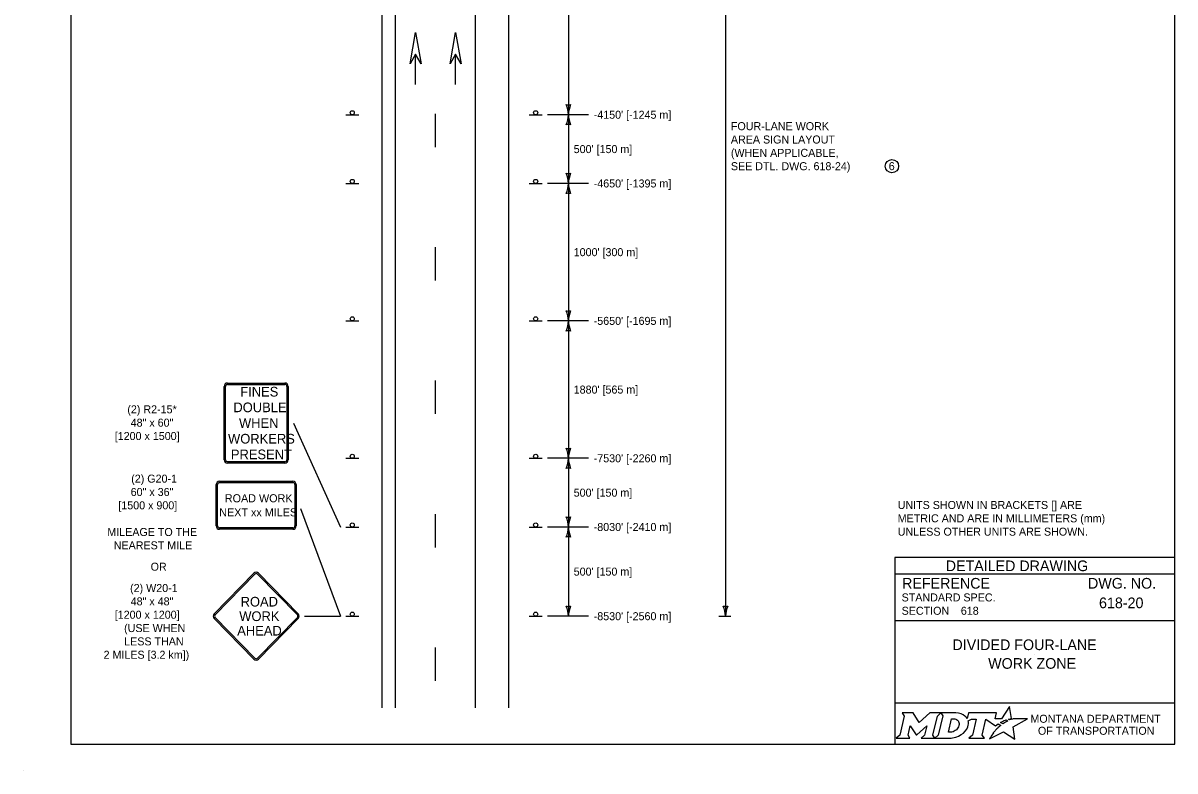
# Model space of a CAD drawing. Extents: x 49991.4 to 50021, y 49987.6 to 50011.4.
# Drawn here: x 49999.98 to 50008.61, y 49999.86 to 50005.47 of the extents above; entities that cross this region are included whole.
import ezdxf

# ---------------------------------------------------------------- set-up
doc = ezdxf.new("R2010")
doc.units = 0
for name, color, linetype in [('Level 1', 7, 'Continuous'), ('Level 2', 7, 'Continuous'), ('Level 3', 7, 'Continuous')]:
    doc.layers.add(name, color=color, linetype=linetype)

msp = doc.modelspace()

# ---------------------------------------------------------------- linework, layer by layer
at = {"layer": 'Level 1'}
for p, q in [((50002.6707, 50000.3351), (50002.6707, 50009.0553)), ((50002.7707, 50000.3351), (50002.7707, 50009.0553)), ((50003.3707, 50000.3351), (50003.3707, 50009.0553)), ((50003.6207, 50000.3351), (50003.6207, 50009.0553)), ((50002.9204, 50005.0081), (50002.9204, 50005.234)), ((50002.9207, 50005.0081), (50002.9207, 50005.234)), ((50003.2204, 50005.0081), (50003.2204, 50005.234)), ((50003.2207, 50005.0081), (50003.2207, 50005.234)), ((50002.3977, 50004.7808), (50002.4937, 50004.7808)), ((50003.0707, 50004.5379), (50003.0707, 50004.7879)), ((50003.7727, 50004.7808), (50003.8687, 50004.7808)), ((50002.3977, 50004.2658), (50002.4937, 50004.2658)), ((50003.7727, 50004.2658), (50003.8687, 50004.2658)), ((50003.0707, 50003.5379), (50003.0707, 50003.7879)), ((50002.3977, 50003.2358), (50002.4937, 50003.2358)), ((50003.7727, 50003.2358), (50003.8687, 50003.2358)), ((50001.4852, 50002.1951), (50001.4852, 50002.7451)), ((50001.4952, 50002.1951), (50001.4952, 50002.7451)), ((50001.5102, 50002.7701), (50001.9402, 50002.7701)), ((50001.5102, 50002.7601), (50001.9402, 50002.7601)), ((50001.9552, 50002.7451), (50001.9552, 50002.1951)), ((50001.9652, 50002.7451), (50001.9652, 50002.1951)), ((50003.0707, 50002.5379), (50003.0707, 50002.7879)), ((50002.3977, 50002.2058), (50002.4937, 50002.2058)), ((50003.7727, 50002.2058), (50003.8687, 50002.2058)), ((50001.9402, 50002.1801), (50001.5102, 50002.1801)), ((50001.9402, 50002.1701), (50001.5102, 50002.1701)), ((50001.4502, 50002.0334), (50002.0002, 50002.0334)), ((50001.4502, 50002.0334), (50002.0002, 50002.0334)), ((50001.4502, 50002.0234), (50002.0002, 50002.0234)), ((50001.4502, 50002.0234), (50002.0002, 50002.0234)), ((50001.4252, 50001.6984), (50001.4252, 50002.0084)), ((50001.4252, 50001.6984), (50001.4252, 50002.0084)), ((50001.4352, 50001.6984), (50001.4352, 50002.0084)), ((50001.4352, 50001.6984), (50001.4352, 50002.0084)), ((50002.0152, 50002.0084), (50002.0152, 50001.6984)), ((50002.0152, 50002.0084), (50002.0152, 50001.6984)), ((50002.0252, 50002.0084), (50002.0252, 50001.6984)), ((50002.0252, 50002.0084), (50002.0252, 50001.6984)), ((50003.0707, 50001.5379), (50003.0707, 50001.7879)), ((50002.0002, 50001.6834), (50001.4502, 50001.6834)), ((50002.0002, 50001.6834), (50001.4502, 50001.6834)), ((50002.0002, 50001.6734), (50001.4502, 50001.6734)), ((50002.0002, 50001.6734), (50001.4502, 50001.6734)), ((50002.3977, 50001.6908), (50002.4937, 50001.6908)), ((50003.7727, 50001.6908), (50003.8687, 50001.6908)), ((50001.7079, 50001.3439), (50001.4099, 50001.0399)), ((50001.7079, 50001.3439), (50001.4099, 50001.0399)), ((50001.7148, 50001.3369), (50001.4168, 50001.0328)), ((50001.7148, 50001.3369), (50001.4168, 50001.0328)), ((50002.0336, 50001.0328), (50001.7356, 50001.3369)), ((50002.0336, 50001.0328), (50001.7356, 50001.3369)), ((50002.0405, 50001.0399), (50001.7425, 50001.3439)), ((50002.0405, 50001.0399), (50001.7425, 50001.3439)), ((50001.4099, 50001.0045), (50001.7079, 50000.7005)), ((50001.4099, 50001.0045), (50001.7079, 50000.7005)), ((50001.4168, 50001.0116), (50001.7148, 50000.7075)), ((50001.4168, 50001.0116), (50001.7148, 50000.7075)), ((50001.7356, 50000.7075), (50002.0336, 50001.0116)), ((50001.7356, 50000.7075), (50002.0336, 50001.0116)), ((50001.7425, 50000.7005), (50002.0405, 50001.0045)), ((50001.7425, 50000.7005), (50002.0405, 50001.0045)), ((50002.3977, 50001.0222), (50002.4937, 50001.0222)), ((50003.7727, 50001.0222), (50003.8687, 50001.0222)), ((50003.0707, 50000.5379), (50003.0707, 50000.7879)), ((49999.9766, 49999.8624), (49999.9766, 49999.8624))]:
    msp.add_line(p, q, dxfattribs=at)
for points in [[(50008.6146, 50011.2628), (50000.3356, 50011.2628), (50000.3356, 50000.0624), (50008.6146, 50000.0624)], [(50002.8787, 50005.1617), (50002.9204, 50005.3982), (50002.9623, 50005.1617), (50002.9204, 50005.2339)], [(50003.1787, 50005.1617), (50003.2204, 50005.3982), (50003.2623, 50005.1617), (50003.2204, 50005.2339)]]:
    msp.add_lwpolyline(points, close=True, dxfattribs=at)
for centre in [(50002.4457, 50004.796), (50003.8207, 50004.796), (50002.4457, 50004.281), (50003.8207, 50004.281), (50002.4457, 50003.251), (50003.8207, 50003.251), (50002.4457, 50002.221), (50003.8207, 50002.221), (50002.4457, 50001.706), (50003.8207, 50001.706), (50002.4457, 50001.0374), (50003.8207, 50001.0374)]:
    msp.add_circle(centre, 0.0152, dxfattribs=at)
for centre, radius, start, end in [((50001.5102, 50002.7451), 0.025, 90, 180), ((50001.5102, 50002.7451), 0.015, 90, 180), ((50001.9402, 50002.7451), 0.025, 0, 90), ((50001.9402, 50002.7451), 0.015, 0, 90), ((50001.5102, 50002.1951), 0.025, 180, 270), ((50001.5102, 50002.1951), 0.015, 180, 270), ((50001.9402, 50002.1951), 0.025, 270, 0), ((50001.9402, 50002.1951), 0.015, 270, 0), ((50001.4502, 50002.0084), 0.025, 90, 180), ((50001.4502, 50002.0084), 0.025, 90, 180), ((50001.4502, 50002.0084), 0.015, 90, 180), ((50001.4502, 50002.0084), 0.015, 90, 180), ((50002.0002, 50002.0084), 0.025, 0, 90), ((50002.0002, 50002.0084), 0.025, 0, 90), ((50002.0002, 50002.0084), 0.015, 0, 90), ((50002.0002, 50002.0084), 0.015, 0, 90), ((50001.4502, 50001.6984), 0.025, 180, 270), ((50001.4502, 50001.6984), 0.025, 180, 270), ((50001.4502, 50001.6984), 0.015, 180, 270), ((50001.4502, 50001.6984), 0.015, 180, 270), ((50002.0002, 50001.6984), 0.025, 270, 360), ((50002.0002, 50001.6984), 0.015, 270, 360), ((50002.0002, 50001.6984), 0.025, 270, 360), ((50002.0002, 50001.6984), 0.015, 270, 360)]:
    msp.add_arc(centre, radius, start, end, dxfattribs=at)
for centre, major_axis, start_param, end_param in [((50001.7252, 50001.3262), (0, 0.025), 5.497787, 7.068583), ((50001.7252, 50001.3262), (0, 0.025), 5.497787, 7.068583), ((50001.7252, 50001.3262), (0, 0.015), 5.497787, 7.068583), ((50001.7252, 50001.3262), (0, 0.015), 5.497787, 7.068583), ((50001.4272, 50001.0222), (0, 0.025), 0.785398, 2.356194), ((50001.4272, 50001.0222), (0, 0.025), 0.785398, 2.356194), ((50001.4272, 50001.0222), (0, 0.015), 0.785398, 2.356194), ((50001.4272, 50001.0222), (0, 0.015), 0.785398, 2.356194), ((50002.0232, 50001.0222), (0, 0.015), 3.926991, 5.497791), ((50002.0232, 50001.0222), (0, 0.015), 3.926991, 5.497791), ((50002.0232, 50001.0222), (0, 0.025), 3.926991, 5.497791), ((50002.0232, 50001.0222), (0, 0.025), 3.926991, 5.497791), ((50001.7252, 50000.7181), (0, -0.025), 5.497787, 7.068576), ((50001.7252, 50000.7181), (0, -0.025), 5.497787, 7.068576), ((50001.7252, 50000.7181), (0, -0.015), 5.497787, 7.068576), ((50001.7252, 50000.7181), (0, -0.015), 5.497787, 7.068576)]:
    msp.add_ellipse(centre, major_axis=major_axis, ratio=0.98, start_param=start_param, end_param=end_param, dxfattribs=at)
at = {"layer": 'Level 2'}
for p, q in [((50008.6146, 50001.4624), (50006.5146, 50001.4624)), ((50006.5146, 50001.4624), (50006.5146, 50000.0624)), ((50008.6146, 50001.3374), (50006.5146, 50001.3374)), ((50008.2507, 50001.1223), (50008.2507, 50001.1223)), ((50008.6146, 50000.9874), (50006.5146, 50000.9874)), ((50007.0089, 50001.0629), (50007.0089, 50001.0629)), ((50007.5646, 50000.7383), (50007.5646, 50000.7383)), ((50008.6146, 50000.3693), (50006.5146, 50000.3693))]:
    msp.add_line(p, q, dxfattribs=at)
for points in [[(50006.5701, 50000.2974), (50006.5842, 50000.274), (50006.5507, 50000.1307), (50006.525, 50000.1082), (50006.6266, 50000.1082), (50006.6131, 50000.131), (50006.6293, 50000.2011), (50006.673, 50000.1321), (50006.6783, 50000.1321), (50006.7534, 50000.2016), (50006.737, 50000.1305), (50006.7123, 50000.1085), (50006.8139, 50000.1085), (50006.8001, 50000.1318), (50006.8333, 50000.2742)], [(50006.8333, 50000.2742), (50006.8586, 50000.2974), (50006.7762, 50000.2974), (50006.6966, 50000.2244), (50006.6521, 50000.2971), (50006.5701, 50000.2974)], [(50006.9722, 50000.2974), (50006.8586, 50000.2974), (50006.8733, 50000.2745), (50006.8394, 50000.1307), (50006.8139, 50000.1085), (50006.9245, 50000.1085)], [(50007.3771, 50000.2447), (50007.3668, 50000.2503), (50007.3784, 50000.2531), (50007.39, 50000.2551), (50007.3726, 50000.3452), (50007.3131, 50000.2539), (50007.2658, 50000.2532), (50007.2761, 50000.2973), (50007.0669, 50000.2974), (50007.0568, 50000.2549), (50007.051, 50000.2632)], [(50006.9962, 50000.2107), (50006.995, 50000.2026), (50006.9918, 50000.1933), (50006.9876, 50000.1851), (50006.982, 50000.1776), (50006.9755, 50000.1707), (50006.9676, 50000.1644), (50006.9593, 50000.1597), (50006.9502, 50000.1558), (50006.9411, 50000.1535), (50006.9319, 50000.1526), (50006.916, 50000.1526), (50006.9396, 50000.2526), (50006.9556, 50000.2526), (50006.9632, 50000.252), (50006.9708, 50000.2501), (50006.9774, 50000.2471), (50006.9835, 50000.2429), (50006.9883, 50000.2379), (50006.992, 50000.2319), (50006.9947, 50000.2257), (50006.9963, 50000.2183), (50006.9963, 50000.2153), (50006.9962, 50000.2107)], [(50007.0636, 50000.2383), (50007.0882, 50000.2514), (50007.1251, 50000.2514), (50007.0965, 50000.1309), (50007.069, 50000.1082), (50007.1852, 50000.1082), (50007.1682, 50000.1311), (50007.1964, 50000.2513), (50007.2677, 50000.1996), (50007.2888, 50000.2147), (50007.3085, 50000.2038)], [(50007.2527, 50000.1479), (50007.2374, 50000.1235), (50007.2327, 50000.116), (50007.2269, 50000.1074), (50007.2246, 50000.1031), (50007.3299, 50000.1562), (50007.4138, 50000.1011), (50007.4007, 50000.1938), (50007.5076, 50000.2522), (50007.4583, 50000.253), (50007.4282, 50000.2534), (50007.4074, 50000.2537), (50007.4006, 50000.2522), (50007.3957, 50000.251), (50007.3873, 50000.2487), (50007.3771, 50000.2447)], [(50007.3267, 50000.2171), (50007.3243, 50000.2154), (50007.306, 50000.225), (50007.3163, 50000.2307), (50007.3204, 50000.2329), (50007.329, 50000.2369), (50007.3347, 50000.2395), (50007.3426, 50000.2425), (50007.3499, 50000.2452), (50007.3617, 50000.2378), (50007.3577, 50000.2357), (50007.3531, 50000.2332), (50007.3489, 50000.231), (50007.3439, 50000.2281), (50007.342, 50000.227), (50007.3393, 50000.2254), (50007.3368, 50000.224), (50007.3345, 50000.2224), (50007.3319, 50000.2206), (50007.3292, 50000.2188), (50007.3267, 50000.2171)], [(50006.9702, 50000.1158), (50006.9786, 50000.1184), (50006.9916, 50000.1238), (50007.012, 50000.1348)], [(50007.2666, 50000.164), (50007.2666, 50000.164)]]:
    msp.add_lwpolyline(points, dxfattribs=at)
msp.add_circle((50006.4925, 50004.3953), 0.05, dxfattribs=at)
for centre, radius, start, end in [((50006.9953, 50000.219), 0.0709, 339.53292, 15.85821), ((50006.9513, 50000.2363), 0.1183, 300.91025, 339.13831)]:
    msp.add_arc(centre, radius, start, end, dxfattribs=at)
for centre, major_axis, ratio, start_param, end_param in [((50006.9701, 50000.25), (0.0834, -0.0037), 0.568097, 0.61298, 1.570796), ((50007.0257, 50000.2573), (0.0361, -0.0295), 0.469099, 1.225588, 1.570796), ((50007.2974, 50000.1941), (-0.0112, -0.0097), 0.021651, 3.157348, 6.283185), ((50006.9248, 50000.2568), (0, 0.1484), 0.987302, 3.139398, 3.456847), ((50007.2597, 50000.1559), (-0.00694, -0.00806), 0.008222, 0, 3.137361), ((50007.2764, 50000.1742), (-0.0098, -0.0102), 0.016458, 3.141593, 6.279097)]:
    msp.add_ellipse(centre, major_axis=major_axis, ratio=ratio, start_param=start_param, end_param=end_param, dxfattribs=at)
at = {"layer": 'Level 3'}
for p, q in [((50005.2445, 50009.0553), (50005.2445, 50001.0222)), ((50004.0659, 50006.9953), (50004.0659, 50004.7808)), ((50004.2159, 50004.7808), (50003.9087, 50004.7808)), ((50004.0659, 50004.7808), (50004.0659, 50004.2658)), ((50004.2159, 50004.2658), (50003.9087, 50004.2658)), ((50004.0659, 50004.2658), (50004.0659, 50003.2358)), ((50004.2159, 50003.2358), (50003.9087, 50003.2358)), ((50004.0659, 50003.2358), (50004.0659, 50002.2058)), ((50002.0052, 50002.4701), (50002.3577, 50001.6908)), ((50004.2159, 50002.2058), (50003.9087, 50002.2058)), ((50004.0659, 50002.2058), (50004.0659, 50001.6908)), ((50002.0565, 50001.8284), (50002.3577, 50001.0222)), ((50004.2159, 50001.6908), (50003.9087, 50001.6908)), ((50004.0659, 50001.6908), (50004.0659, 50001.0222)), ((50002.0877, 50001.0222), (50002.3577, 50001.0222)), ((50004.2159, 50001.0222), (50003.9087, 50001.0222)), ((50005.1935, 50001.0222), (50005.2845, 50001.0222))]:
    msp.add_line(p, q, dxfattribs=at)
for centre, radius, start, end in [((50004.0659, 50004.909), 0.0548, 252.13882, 287.86118), ((50003.8332, 50004.7693), 0.233, 2.82731, 22.07716), ((50003.8437, 50004.79), 0.2223, 337.45601, 357.63952), ((50004.288, 50004.7716), 0.2223, 157.45601, 177.63952), ((50004.2986, 50004.7923), 0.233, 182.82731, 202.07716), ((50004.0659, 50004.6526), 0.0548, 72.13882, 107.86118), ((50004.0659, 50004.394), 0.0548, 252.13882, 287.86118), ((50003.8332, 50004.2543), 0.233, 2.82731, 22.07716), ((50003.8437, 50004.275), 0.2223, 337.45601, 357.63952), ((50004.288, 50004.2566), 0.2223, 157.45601, 177.63952), ((50004.2986, 50004.2773), 0.233, 182.82731, 202.07716), ((50004.0659, 50004.1376), 0.0548, 72.13882, 107.86118), ((50004.0659, 50003.364), 0.0548, 252.13882, 287.86118), ((50003.8332, 50003.2243), 0.233, 2.82731, 22.07716), ((50004.288, 50003.2266), 0.2223, 157.45601, 177.63952), ((50003.8437, 50003.245), 0.2223, 337.45601, 357.63952), ((50004.2986, 50003.2473), 0.233, 182.82731, 202.07716), ((50004.0659, 50003.1076), 0.0548, 72.13882, 107.86118), ((50004.0659, 50002.334), 0.0548, 252.13882, 287.86118), ((50003.8332, 50002.1943), 0.233, 2.82731, 22.07716), ((50004.288, 50002.1966), 0.2223, 157.45601, 177.63952), ((50003.8437, 50002.215), 0.2223, 337.45601, 357.63952), ((50004.2986, 50002.2173), 0.233, 182.82731, 202.07716), ((50004.0659, 50002.0776), 0.0548, 72.13882, 107.86118), ((50004.0659, 50001.819), 0.0548, 252.13882, 287.86118), ((50003.8332, 50001.6793), 0.233, 2.82731, 22.07716), ((50004.288, 50001.6816), 0.2223, 157.45601, 177.63952), ((50003.8437, 50001.7), 0.2223, 337.45601, 357.63952), ((50004.2986, 50001.7023), 0.233, 182.82731, 202.07716), ((50004.0659, 50001.5626), 0.0548, 72.13882, 107.86118), ((50004.0659, 50001.1504), 0.0548, 252.13882, 287.86118), ((50003.8332, 50001.0107), 0.233, 2.82731, 22.07716), ((50004.288, 50001.013), 0.2223, 157.45601, 177.63952), ((50005.2445, 50001.1504), 0.0548, 252.13882, 287.86118), ((50005.0118, 50001.0107), 0.233, 2.82731, 22.07716), ((50005.4667, 50001.013), 0.2223, 157.45601, 177.63952)]:
    msp.add_arc(centre, radius, start, end, dxfattribs=at)

# ---------------------------------------------------------------- texts
at = {"layer": 'Level 1'}
for s, height, p in [('FINES', 0.0725, (50001.6055, 50002.6688)), ('DOUBLE', 0.0725, (50001.554, 50002.5513)), ('WHEN', 0.0725, (50001.596, 50002.4338)), ('WORKERS', 0.0725, (50001.5138, 50002.3163)), ('PRESENT', 0.0725, (50001.5352, 50002.1988)), ('ROAD WORK', 0.0605, (50001.4898, 50001.8759)), ('ROAD WORK', 0.0605, (50001.4898, 50001.8759)), ('NEXT xx MILES', 0.0605, (50001.4476, 50001.7704)), ('NEXT xx MILES', 0.0605, (50001.4476, 50001.7704)), ('ROAD', 0.0725, (50001.6082, 50001.0947)), ('ROAD', 0.0725, (50001.6082, 50001.0947)), ('WORK', 0.0725, (50001.5981, 50000.986)), ('WORK', 0.0725, (50001.5981, 50000.986)), ('AHEAD', 0.0725, (50001.5826, 50000.8773)), ('AHEAD', 0.0725, (50001.5826, 50000.8773))]:
    msp.add_text(s, height=height, dxfattribs=at).set_placement(p)
at = {"layer": 'Level 2'}
for s, height, p in [("-4150' [-1245 m]", 0.06, (50004.2559, 50004.7508)), ('FOUR-LANE WORK', 0.06, (50005.2846, 50004.6652)), ('AREA SIGN LAYOUT', 0.06, (50005.2846, 50004.5652)), ("500' [150 m]", 0.06, (50004.1059, 50004.4933)), ('(WHEN APPLICABLE,', 0.06, (50005.2846, 50004.4652)), ('SEE DTL. DWG. 618-24)', 0.06, (50005.2846, 50004.3652)), ('6', 0.06, (50006.4683, 50004.3654)), ("-4650' [-1395 m]", 0.06, (50004.2559, 50004.2358)), ("1000' [300 m]", 0.06, (50004.1059, 50003.7208)), ("-5650' [-1695 m]", 0.06, (50004.2559, 50003.2058)), ("1880' [565 m]", 0.06, (50004.1059, 50002.6908)), ('(2) R2-15*', 0.06, (50000.7587, 50002.5428)), ('48" x 60"', 0.06, (50000.7838, 50002.4428)), ('[1200 x 1500]', 0.06, (50000.6644, 50002.3428)), ("-7530' [-2260 m]", 0.06, (50004.2559, 50002.1758)), ('(2) G20-1', 0.06, (50000.7878, 50002.0234)), ('60" x 36"', 0.06, (50000.7838, 50001.9234)), ("500' [150 m]", 0.06, (50004.1059, 50001.9183)), ('[1500 x 900]', 0.06, (50000.6913, 50001.8234)), ('UNITS SHOWN IN BRACKETS [] ARE ', 0.06, (50006.5355, 50001.8259)), ('METRIC AND ARE IN MILLIMETERS (mm) ', 0.06, (50006.5355, 50001.7259)), ('MILEAGE TO THE', 0.06, (50000.6087, 50001.6234)), ("-8030' [-2410 m]", 0.06, (50004.2559, 50001.6608)), ('UNLESS OTHER UNITS ARE SHOWN.', 0.06, (50006.5355, 50001.6259)), ('NEAREST MILE', 0.06, (50000.6569, 50001.5234)), ('OR', 0.06, (50000.9335, 50001.3634)), ('DETAILED DRAWING', 0.0799, (50006.8956, 50001.3599)), ("500' [150 m]", 0.06, (50004.1059, 50001.3265)), ('(2) W20-1', 0.06, (50000.7794, 50001.2034)), ('REFERENCE', 0.08, (50006.5682, 50001.229)), ('DWG. NO.', 0.08, (50007.9624, 50001.229)), ('48" x 48"', 0.06, (50000.7838, 50001.1034)), ('STANDARD SPEC.', 0.06, (50006.5649, 50001.133)), ('618-20', 0.08, (50008.0451, 50001.0823)), ('[1200 x 1200]', 0.06, (50000.6644, 50001.0034)), ('SECTION', 0.06, (50006.5649, 50001.033)), ('618', 0.06, (50007.0089, 50001.0329)), ("-8530' [-2560 m]", 0.06, (50004.2559, 50000.9922)), ('(USE WHEN', 0.06, (50000.7345, 50000.9034)), ('LESS THAN', 0.06, (50000.7351, 50000.8034)), ('DIVIDED FOUR-LANE', 0.08, (50006.946, 50000.7683)), ('2 MILES [3.2 km])', 0.06, (50000.5807, 50000.7034)), ('WORK ZONE', 0.08, (50007.2139, 50000.6283)), ('MONTANA DEPARTMENT', 0.06, (50007.5308, 50000.2236)), ('OF TRANSPORTATION', 0.06, (50007.587, 50000.1336))]:
    msp.add_text(s, height=height, dxfattribs=at).set_placement(p)

doc.saveas('drawing.dxf')
